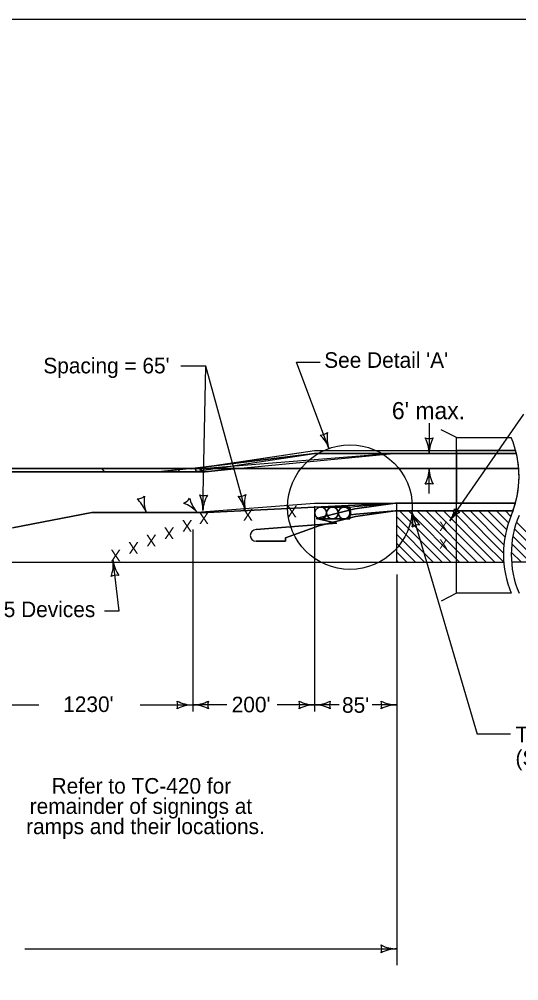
# Model space of a CAD drawing. Extents: x 10133 to 2270741, y 5363 to 1733450.
# Drawn here: x 30024 to 30665, y 8710 to 9944 of the extents above; entities that cross this region are included whole.
import ezdxf

# ---------------------------------------------------------------- set-up
doc = ezdxf.new("R2010")
doc.units = 0
for name, color, linetype in [('dsnNonPlotable', 7, 'Continuous'), ('dsnStdBlockModified', 7, 'Continuous'), ('dsnStdBorder', 7, 'Continuous'), ('Level 12', 7, 'Continuous'), ('Level 2', 7, 'Continuous'), ('SheetBorder', 7, 'Continuous'), ('SheetText', 7, 'Continuous')]:
    doc.layers.add(name, color=color, linetype=linetype)

# ---------------------------------------------------------------- blocks, each defined once
blk = doc.blocks.new('LT')
at = {"layer": 'dsnStdBorder'}
for centre, radius, start, end in [((-3.56, 0), 1.64, 342.2666, 17.7333), ((0, 4.25), 4.25, 241.9275, 270), ((0, -4.25), 4.25, 90, 118.0725)]:
    blk.add_arc(centre, radius, start, end, dxfattribs=at)

msp = doc.modelspace()

# ---------------------------------------------------------------- linework, layer by layer
at = {"layer": 'dsnNonPlotable'}
for p, q in [((30585.2, 9407.1), (30565.2, 9417.1)), ((30246.7, 9363.1), (30403, 9386.6)), ((30403, 9386.6), (30661.8, 9386.6)), ((30504.2, 9386.6), (30661.8, 9386.6)), ((30249.8, 9367.1), (30487.2, 9367.1)), ((30487.2, 9367.1), (30664.8, 9367.1)), ((30246.7, 9310.8), (30403, 9322.8)), ((30403, 9322.8), (30506.3, 9322.8)), ((30660.6, 9322.8), (30634.3, 9322.8)), ((30631.1, 9312.8), (30657.4, 9312.8)), ((30585.2, 9207.1), (30565.2, 9197.1))]:
    msp.add_line(p, q, dxfattribs=at)
for points in [[(30655.2, 9207.1), (30585.2, 9207.1), (30585.2, 9407.1), (30655.2, 9407.1)], [(28167.7, 9363.1), (30246.7, 9363.1)], [(30448.3, 9317.7), (30454.4, 9318.5), (30506.3, 9322.8)], [(30660.6, 9322.8), (30506.3, 9322.8)], [(30448.3, 9317.7), (30449.6, 9307.8), (30449.6, 9307.8)], [(30449.6, 9307.8), (30455.7, 9308.6), (30506.3, 9312.8)], [(30506.3, 9312.8), (30657.4, 9312.8)]]:
    msp.add_lwpolyline(points, dxfattribs=at)
for centre, start, end in [((30535.2, 9357.1), 337.3801, 22.6199), ((30775.2, 9257.1), 157.3801, 202.6199), ((30785.2, 9257.1), 157.3801, 202.6199)]:
    msp.add_arc(centre, 130, start, end, dxfattribs=at)
at = {"layer": 'dsnStdBlockModified'}
for p, q in [((30448.3, 9317.7), (30410.8, 9317.7)), ((30448.3, 9302.7), (30448.3, 9317.7)), ((30410.8, 9302.7), (30448.3, 9302.7))]:
    msp.add_line(p, q, dxfattribs=at)
for centre in [(30410.8, 9310.2), (30410.8, 9310.2), (30425.8, 9310.2), (30425.8, 9310.2), (30440.8, 9310.2), (30440.8, 9310.2)]:
    msp.add_circle(centre, 7.5, dxfattribs=at)
at = {"layer": 'dsnStdBorder'}
for p, q in [((30508.3, 9247.1), (30508.3, 9312.8)), ((30512, 9312.8), (30577.7, 9247.1)), ((30523.3, 9312.8), (30589, 9247.1)), ((30534.6, 9312.8), (30600.3, 9247.1)), ((30545.9, 9312.8), (30611.7, 9247.1)), ((30557.2, 9312.8), (30623, 9247.1)), ((30568.5, 9312.8), (30634.3, 9247.1)), ((30579.9, 9312.8), (30619.8, 9272.8)), ((30591.2, 9312.8), (30645.2, 9258.7)), ((30602.5, 9312.8), (30645.8, 9269.5)), ((30613.8, 9312.8), (30647.2, 9279.4)), ((30625.1, 9312.8), (30649.1, 9288.8)), ((30636.4, 9312.8), (30651.7, 9297.5)), ((30647.7, 9312.8), (30654.7, 9305.8)), ((30508.3, 9305.2), (30566.4, 9247.1)), ((30662, 9298.5), (30713.5, 9247.1)), ((30508.3, 9293.9), (30555.1, 9247.1)), ((30508.3, 9282.6), (30543.8, 9247.1)), ((30659.4, 9289.8), (30702.2, 9247.1)), ((30508.3, 9271.2), (30532.5, 9247.1)), ((30619.8, 9272.8), (30645.6, 9247.1)), ((30655.9, 9270.7), (30679.5, 9247.1)), ((30657.3, 9280.6), (30690.8, 9247.1)), ((30508.3, 9259.9), (30521.1, 9247.1)), ((30655.2, 9260), (30668.2, 9247.1)), ((30508.3, 9248.6), (30509.8, 9247.1)), ((30619, 9251), (30623, 9247.1)), ((30655.5, 9248.5), (30656.9, 9247.1))]:
    msp.add_line(p, q, dxfattribs=at)
for centre in [(30410.8, 9310.2), (30425.8, 9310.2), (30440.8, 9310.2)]:
    msp.add_circle(centre, 7.5, dxfattribs=at)
at = {"layer": 'Level 12'}
for p, q in [((30263.2, 9498.8), (30231.4, 9498.8)), ((30259.6, 9313.2), (30263.2, 9498.8)), ((30314.1, 9313.2), (30263.2, 9498.8)), ((30421.2, 9393), (30379.8, 9503.8)), ((30379.8, 9503.8), (30410, 9503.8)), ((30576.6, 9300.1), (30671.3, 9436.9)), ((30549.9, 9425.3), (30549.9, 9386.6)), ((30540, 9386.6), (30557.9, 9386.6)), ((30539, 9367.1), (30557.9, 9367.1)), ((30549.9, 9335.1), (30549.9, 9367.1)), ((30403, 9319), (30403, 9055.2)), ((30527.4, 9312.8), (30611.6, 9026.4)), ((30246.7, 9289), (30246.7, 9055.2)), ((30152.3, 9184.5), (30144.3, 9249.2)), ((30508.3, 9231.3), (30508.3, 8729.9)), ((30133.5, 9184.5), (30152.3, 9184.5)), ((29981.7, 9063.7), (30049.3, 9063.7)), ((30179, 9063.7), (30246.7, 9063.7)), ((30290.3, 9063.7), (30246.7, 9063.7)), ((30403, 9063.7), (30355, 9063.7)), ((30434.6, 9063.7), (30403, 9063.7)), ((30508.3, 9063.7), (30476.7, 9063.7)), ((30654.4, 9026.4), (30611.6, 9026.4)), ((30031.3, 8750.6), (30508.3, 8750.6))]:
    msp.add_line(p, q, dxfattribs=at)
for centre, radius, start, end in [((30409.6, 9426.6), 16.4, 271.2783, 306.745), ((30381.1, 9379.1), 42.5, 19.0117, 47.0842), ((30461.4, 9406.8), 42.5, 170.9392, 199.0117), ((30549.9, 9422.2), 16.4, 252.2666, 287.7334), ((30507.4, 9386.6), 42.5, 0, 28.0725), ((30592.4, 9386.6), 42.5, 151.9275, 180), ((30507.4, 9367.1), 42.5, 331.9275, 0), ((30592.4, 9367.1), 42.5, 180, 208.0725), ((30549.9, 9331.4), 16.4, 72.2666, 107.7334), ((30261.1, 9348.8), 16.4, 249.8952, 285.3619), ((30217.2, 9315), 42.5, 357.6286, 25.7011), ((30302.1, 9311.5), 42.5, 149.5561, 177.6286), ((30306.2, 9347.9), 16.4, 264.965, 300.4317), ((30355.5, 9322.5), 42.5, 164.6259, 192.6984), ((30272.6, 9303.8), 42.5, 12.6984, 40.7709), ((30486.6, 9300.8), 42.5, 348.3144, 16.3869), ((30568.1, 9324.8), 42.5, 196.3869, 224.4594), ((30537.4, 9278.6), 16.4, 88.6536, 124.1203), ((30102.1, 9244), 42.5, 339.0174, 7.0899), ((30186.5, 9254.4), 42.5, 187.0899, 215.1624), ((30148.7, 9213.8), 16.4, 79.3566, 114.8233), ((30211, 9063.7), 16.4, 342.2666, 17.7334), ((30246.7, 9106.2), 42.5, 241.9275, 270), ((30246.7, 9021.2), 42.5, 90, 118.0725), ((30246.7, 9106.2), 42.5, 270, 298.0725), ((30246.7, 9021.2), 42.5, 61.9275, 90), ((30282.3, 9063.7), 16.4, 162.2666, 197.7334), ((30367.4, 9063.7), 16.4, 342.2666, 17.7334), ((30403, 9106.2), 42.5, 241.9275, 270), ((30403, 9021.2), 42.5, 90, 118.0725), ((30403, 9106.2), 42.5, 270, 298.0725), ((30403, 9021.2), 42.5, 61.9275, 90), ((30438.6, 9063.7), 16.4, 162.2666, 197.7334), ((30472.6, 9063.7), 16.4, 342.2666, 17.7334), ((30508.3, 9106.2), 42.5, 241.9275, 270), ((30508.3, 9021.2), 42.5, 90, 118.0725), ((30472.6, 8750.6), 16.4, 342.2666, 17.7334), ((30508.3, 8793.1), 42.5, 241.9275, 270), ((30508.3, 8708.1), 42.5, 90, 118.0725)]:
    msp.add_arc(centre, radius, start, end, dxfattribs=at)
at = {"layer": 'Level 2'}
for p, q in [((30245.5, 9366.9), (30403, 9390.6)), ((30403, 9386.6), (30246.2, 9367.1)), ((30246.2, 9367.1), (30403, 9386.6)), ((30249.8, 9367.1), (30403, 9390.6)), ((30504.2, 9386.6), (30268.7, 9367.7)), ((30303.7, 9367.1), (30504.2, 9386.6)), ((30403, 9390.6), (30660.8, 9390.6)), ((30403, 9390.6), (30549.7, 9390.6)), ((30549.9, 9386.6), (30403, 9386.6)), ((30403, 9386.6), (30540, 9386.6)), ((30540, 9386.6), (30549.9, 9386.6)), ((30557.9, 9386.6), (30549.9, 9386.6)), ((30549.9, 9386.6), (30557.9, 9386.6)), ((30550, 9390.6), (30585.2, 9390.6)), ((30585.2, 9386.6), (30557.9, 9386.6)), ((30557.9, 9386.6), (30585.2, 9386.6)), ((30585.2, 9390.6), (30585.2, 9386.6)), ((30585.2, 9390.6), (30585.2, 9386.6)), ((30661.8, 9386.6), (30585.2, 9386.6)), ((30585.2, 9386.6), (30585.2, 9367.1)), ((30585.2, 9386.6), (30585.2, 9367.1)), ((30585.2, 9386.6), (30661.8, 9386.6)), ((30634.5, 9390.6), (30660.9, 9390.6)), ((28171.7, 9367.1), (30262.4, 9367.1)), ((30249.8, 9367.1), (29954.1, 9367.1)), ((29957.3, 9363.1), (30251.4, 9363.1)), ((30251.4, 9363.1), (29957.3, 9363.1)), ((30133.2, 9363.1), (30130.3, 9367.1)), ((30130.3, 9367.1), (30255.4, 9367.1)), ((30260.4, 9363.1), (30133.2, 9363.1)), ((30243.5, 9367.1), (30202.2, 9363.1)), ((30202.2, 9363.1), (30260.4, 9363.1)), ((30245.8, 9367.1), (30205.7, 9363.1)), ((30205.7, 9363.1), (30251.4, 9363.1)), ((30225.6, 9367.1), (30249.8, 9367.1)), ((30230.4, 9363.1), (30225.6, 9367.1)), ((30251.4, 9363.1), (30230.4, 9363.1)), ((30245.3, 9367.1), (30243.5, 9367.1)), ((30255.4, 9367.1), (30245.3, 9367.1)), ((30246.2, 9367.1), (30249.8, 9367.1)), ((30487.2, 9367.1), (30246.2, 9367.1)), ((30251.4, 9363.1), (30249.8, 9367.1)), ((30249.8, 9367.1), (30251.4, 9363.1)), ((30255.4, 9367.1), (30260.4, 9363.1)), ((30260.4, 9363.1), (30255.4, 9367.1)), ((30268.7, 9367.7), (30262.4, 9367.1)), ((30262.4, 9367.1), (30303.7, 9367.1)), ((30262.6, 9363.1), (30303.7, 9367.1)), ((30487.2, 9367.1), (30303.7, 9367.1)), ((30539, 9367.1), (30487.2, 9367.1)), ((30549.9, 9367.1), (30539, 9367.1)), ((30549.9, 9347.8), (30549.9, 9367.1)), ((30585.2, 9367.1), (30664.8, 9367.1)), ((30664.8, 9367.1), (30585.2, 9367.1)), ((30585.2, 9367.1), (30585.2, 9322.8)), ((30585.2, 9322.8), (30585.2, 9367.1)), ((30506.3, 9322.8), (30265.3, 9310.8)), ((30265.3, 9310.8), (30506.3, 9322.8)), ((30508.3, 9322.9), (30506.3, 9322.8)), ((30506.3, 9322.8), (30660.6, 9322.8)), ((30506.3, 9322.8), (30585.2, 9322.8)), ((30508.3, 9312.8), (30508.3, 9322.9)), ((30585.2, 9322.8), (30660.6, 9322.8)), ((30117.1, 9310.8), (30015.5, 9291.3)), ((30015.5, 9291.3), (30117.1, 9310.8)), ((30232.5, 9310.8), (30117.1, 9310.8)), ((30117.1, 9310.8), (30265.3, 9310.8)), ((30185.9, 9313.2), (30186.7, 9311.1)), ((30265.3, 9310.8), (30232.5, 9310.8)), ((30232.7, 9310.5), (30232.5, 9310.8)), ((30250.5, 9313), (30252.2, 9311.1)), ((30252.2, 9311.1), (30250.5, 9313)), ((30411.2, 9317.7), (30425.8, 9317.7)), ((30426.2, 9317.7), (30441.2, 9317.7)), ((30441.2, 9317.7), (30448.3, 9317.7)), ((30449.6, 9307.8), (30448.3, 9317.7)), ((30448.3, 9317.7), (30448.3, 9310.2)), ((30448.3, 9309.8), (30448.3, 9302.7)), ((30657.4, 9312.8), (30506.3, 9312.8)), ((30508.3, 9247.1), (30508.3, 9312.8)), ((30327.9, 9288.8), (30431.3, 9297.3)), ((30431.3, 9297.3), (30327.9, 9288.8)), ((30425.4, 9302.7), (30410.8, 9302.7)), ((30440.4, 9302.7), (30425.4, 9302.7)), ((30448.3, 9302.7), (30440.4, 9302.7)), ((30365.4, 9273.8), (30327.9, 9273.8)), ((30327.9, 9273.8), (30365.4, 9273.8)), ((30365.4, 9273.8), (30365.4, 9278.1)), ((28171.7, 9247.1), (30467.9, 9247.1)), ((29565.5, 9247.1), (30396.1, 9247.1)), ((30396.1, 9247.1), (30645.6, 9247.1)), ((30826, 9247.1), (30655.6, 9247.1))]:
    msp.add_line(p, q, dxfattribs=at)
for points in [[(30660.8, 9390.6), (30634.5, 9390.6), (30585.2, 9390.6)], [(30660.8, 9390.6), (30660.8, 9390.6)], [(30205.7, 9363.1), (30261.6, 9363.1), (30262.6, 9363.1)], [(30261.6, 9363.1), (30257.3, 9363.1), (30205.7, 9363.1)], [(30303.7, 9367.1), (30262.4, 9367.1), (30245.8, 9367.1)], [(30303.7, 9367.1), (30262.6, 9363.1), (30261.6, 9363)], [(30261.6, 9363), (30261.6, 9363.1)], [(30585.2, 9367.1), (30557.9, 9367.1), (30549.9, 9367.1), (30539, 9367.1), (30487.2, 9367.1)], [(30585.2, 9367.1), (30557.9, 9367.1), (30549.9, 9367.1)], [(30431.3, 9297.3), (30404.9, 9303.1), (30454.4, 9315.5), (30506.3, 9322.8)], [(30506.3, 9322.8), (30454.4, 9315.5), (30404.9, 9303.1), (30431.3, 9297.3)], [(30448.3, 9317.7), (30454.4, 9318.5), (30506, 9322.8), (30506.3, 9322.8)], [(30506.3, 9322.8), (30506.3, 9322.8)], [(30186.7, 9311.1), (30186.7, 9311.1), (30185.9, 9313.2)], [(30186.7, 9311.1), (30186.7, 9311.1)], [(30252.2, 9311.1), (30252.2, 9311.1)], [(30252.2, 9311.1), (30252.2, 9311.1)], [(30508.3, 9312.8), (30506.3, 9312.8), (30455.6, 9305.7), (30408.3, 9293.7), (30365.4, 9278.1)], [(30365.4, 9278.1), (30408.3, 9293.7), (30455.6, 9305.7), (30506.3, 9312.8), (30508.3, 9312.8)], [(30411.2, 9317.7), (30411.2, 9317.7)], [(30418.3, 9309.8), (30418.3, 9309.8)], [(30426.2, 9317.7), (30426.2, 9317.7)], [(30433.3, 9309.8), (30433.3, 9309.8)], [(30441.2, 9317.7), (30441.2, 9317.7)], [(30441.2, 9317.7), (30441.2, 9317.7)], [(30448.3, 9309.8), (30448.3, 9309.8)], [(30506.3, 9312.8), (30455.7, 9308.6), (30449.6, 9307.8)], [(30425.4, 9302.7), (30425.4, 9302.7)], [(30425.4, 9302.7), (30425.4, 9302.7)], [(30440.4, 9302.7), (30440.4, 9302.7)], [(30440.4, 9302.7), (30440.4, 9302.7)], [(30365.4, 9278.1), (30365.4, 9278.1), (30365.4, 9273.8)], [(30396.1, 9247.1), (30467.9, 9247.1), (30508.3, 9247.1)]]:
    msp.add_lwpolyline(points, dxfattribs=at)
for centre, radius, start, end in [((30507.4, 9386.6), 42.5, 0, 5.4005), ((30592.4, 9386.6), 42.5, 174.5995, 179.9824), ((30507.4, 9386.6), 42.5, 0, 0.0176), ((30535.2, 9357.1), 130, 13.1184, 14.9371), ((30535.2, 9357.1), 130, 4.4117, 13.1184), ((30507.4, 9367.1), 42.5, 331.9275, 0), ((30535.2, 9357.1), 130, 344.7177, 4.4117), ((30549.9, 9331.4), 16.4, 90, 107.7334), ((30174.4, 9344.6), 16.4, 272.4117, 307.8784), ((30174.4, 9344.6), 16.4, 272.4117, 307.8784), ((30146.8, 9296.5), 42.5, 23.0899, 48.2175), ((30146.8, 9296.5), 42.5, 23.0899, 48.2175), ((30226.6, 9325.8), 42.5, 172.0726, 200.1275), ((30226.6, 9325.8), 42.5, 172.0726, 200.1275), ((30228.3, 9337.6), 16.4, 294.2304, 329.6971), ((30228.4, 9337.6), 16.4, 294.2304, 329.6971), ((30220.6, 9282.7), 42.5, 41.9813, 70.0362), ((30220.6, 9282.6), 42.5, 41.9813, 70.0362), ((30283.8, 9339.5), 42.5, 193.8912, 218.5415), ((30283.8, 9339.5), 42.5, 193.8912, 218.5415), ((30535.2, 9357.1), 130, 340.0928, 344.7177), ((30146.8, 9296.5), 42.5, 20.1451, 20.1627), ((30267.1, 9335.5), 42.5, 215.5389, 216.0818), ((30198.4, 9285.4), 42.5, 36.0994, 36.117), ((30267.1, 9335.5), 42.5, 216.0989, 216.0994), ((30283.8, 9339.5), 42.5, 221.9461, 221.9637), ((30410.8, 9310.2), 7.5, 267.0001, 356.9999), ((30410.8, 9310.2), 7.5, 270, 357.0043), ((30410.8, 9310.1), 7.55, 3.3189, 86.8597), ((30410.8, 9310.2), 7.5, 42.0293, 86.9975), ((30410.8, 9310.1), 7.55, 3.3337, 42.1724), ((30425.8, 9310.2), 7.5, 267, 266.9552), ((30425.8, 9310.2), 7.5, 90.3225, 176.9869), ((30425.8, 9310.2), 7.5, 182.9876, 266.9583), ((30425.8, 9310.2), 7.5, 267.0031, 357.0043), ((30425.8, 9310.1), 7.55, 3.323, 86.8556), ((30425.8, 9310.2), 7.5, 40.9459, 87.0002), ((30425.8, 9310.1), 7.55, 3.4004, 41.098), ((30440.8, 9310.2), 7.5, 86.9958, 177.0042), ((30440.8, 9310.2), 7.5, 86.9975, 176.9187), ((30440.8, 9310.2), 7.5, 177.006, 266.994), ((30440.8, 9310.2), 7.5, 182.9876, 267.0031), ((30440.8, 9310.2), 7.51, 267.1005, 356.8995), ((30440.8, 9310.2), 7.5, 267.0031, 357.0041), ((30440.8, 9310.2), 7.5, 356.9998, 87.0002), ((30440.8, 9310.2), 7.5, 0, 86.9975), ((30327.9, 9281.3), 7.5, 90, 270), ((30327.9, 9281.3), 7.5, 90, 270)]:
    msp.add_arc(centre, radius, start, end, dxfattribs=at)
at = {"layer": 'SheetBorder'}
msp.add_lwpolyline([(28132.5, 9944), (31267.5, 9944), (31267.5, 7924), (28132.5, 7924)], close=True, dxfattribs=at)
at = {"layer": 'SheetText'}
msp.add_circle((30448.3, 9317.7), 80, dxfattribs=at)

# ---------------------------------------------------------------- block references
at = {"layer": 'Level 12', "xscale": 7.999600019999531, "yscale": 7.999200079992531, "rotation": -124.70293665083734}
msp.add_blockref('LT', (30576.6, 9300.1), dxfattribs=at)

# ---------------------------------------------------------------- texts
at = {"layer": 'dsnStdBorder'}
for p in [(30380.7, 9319.4), (30267.6, 9311.1), (30324.1, 9315.4), (30246.1, 9301.2), (30200.1, 9282.3), (30223, 9291.8), (30177.3, 9272.8), (30154.4, 9263.3)]:
    msp.add_text('X', height=15, rotation=180, dxfattribs=at).set_placement(p)
for s, height, p in [('X', 12, (30562.8, 9286.9)), ('X', 12, (30562.8, 9264.3)), ('Refer to TC-420 for', 20, (30065.5, 8949.9)), ('remainder of signings at', 20, (30037.4, 8923.9)), ('ramps and their locations.', 20, (30032.8, 8897.9))]:
    msp.add_text(s, height=height, dxfattribs=at).set_placement(p)
at = {"layer": 'Level 12'}
for s, height, p in [("See Detail 'A'", 20, (30415.3, 9496.5)), ("Spacing = 65'", 20, (30054.9, 9489.4)), ("6' max.", 22, (30502.1, 9430.6)), ('5 Devices', 20, (30004.1, 9176.5)), ("1230'", 20, (30080.4, 9054.7)), ("200'", 20, (30296.6, 9054.3)), ("85'", 20, (30438.1, 9053.7)), ('Temporary Barrier Rail', 20, (30660.7, 9015.8)), ('(See Typical 8210)', 20, (30660.7, 8985.8))]:
    msp.add_text(s, height=height, dxfattribs=at).set_placement(p)

doc.saveas('drawing.dxf')
